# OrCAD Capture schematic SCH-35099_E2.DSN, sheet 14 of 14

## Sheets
14 09 Pmod/UART/I3C: size C
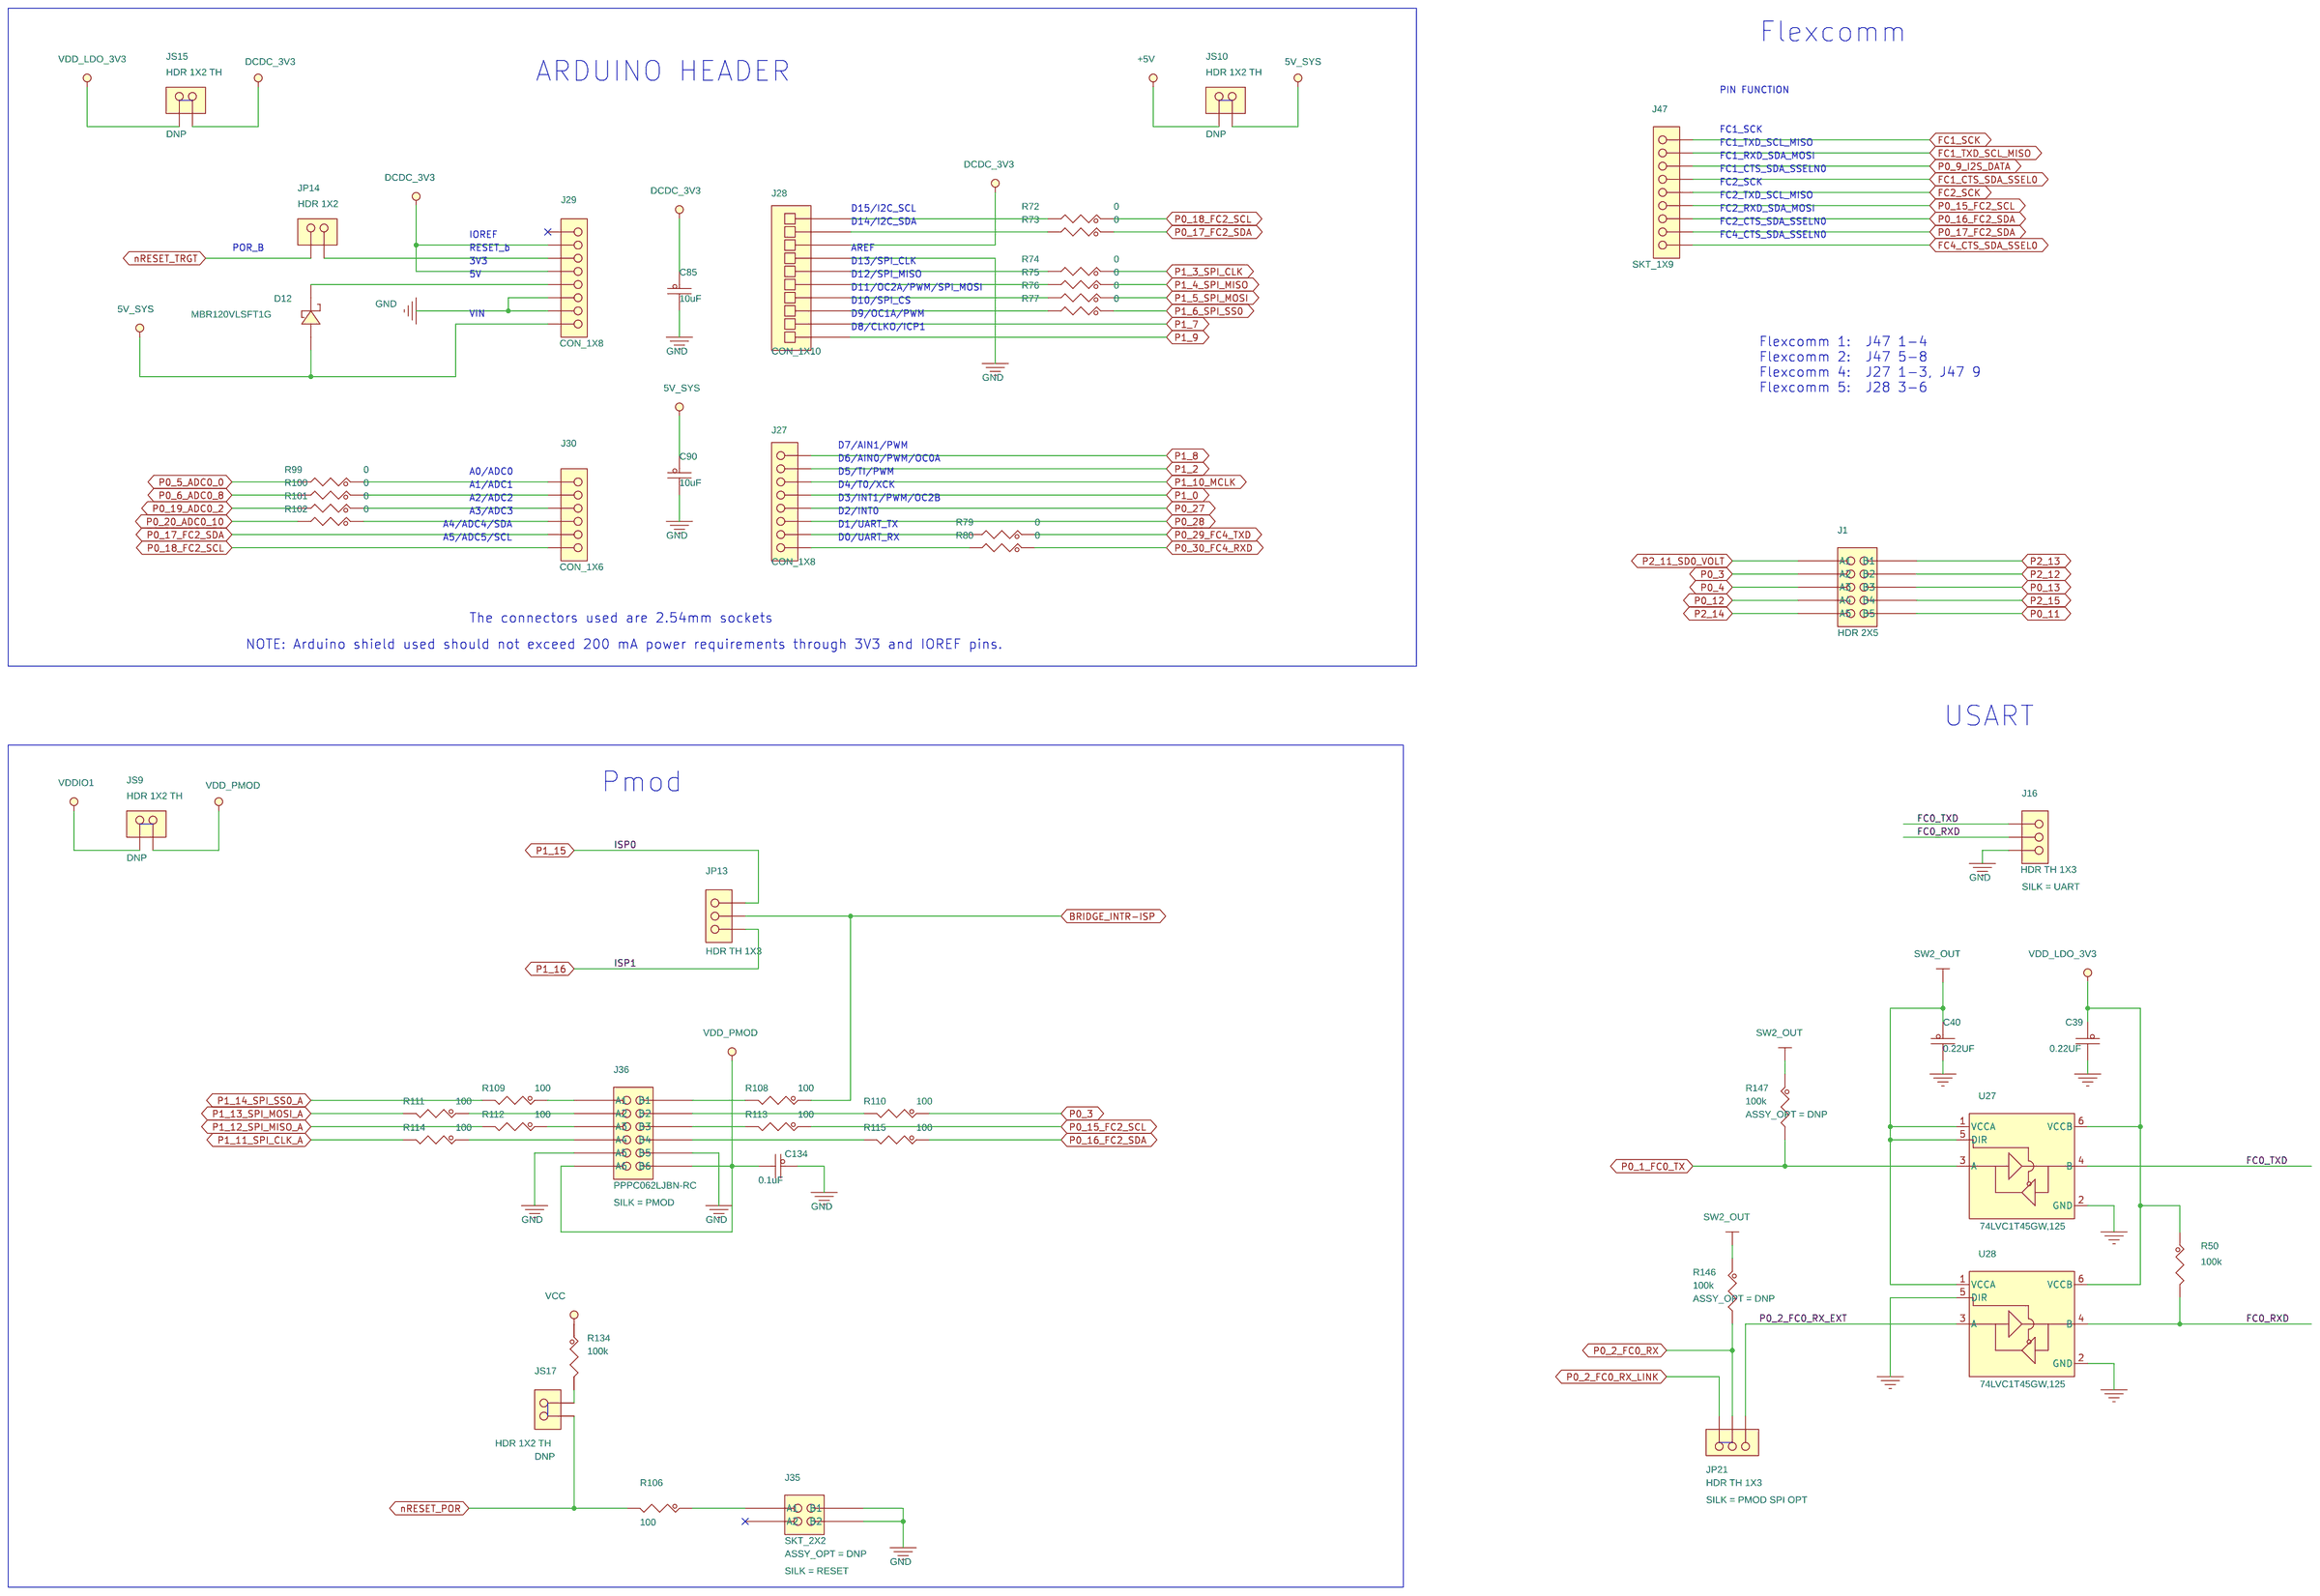
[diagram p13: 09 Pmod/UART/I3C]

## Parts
C39  0.22UF  [CC0402_25]
C40  0.22UF  [CC0402_25]
C85  10uF  [CC0603_OV]
C90  10uF  [CC0603_OV]
C134  0.1uF  [CC0402_25]
D12  MBR120VLSFT1G  [SOD-123]
J1  HDR 2X5  [HDR205]
J16  HDR TH 1X3  [HDR103]
J27  CON_1X8  [con_1x8_skt_2p54_th]
J28  CON_1X10  [HDR110]
J29  CON_1X8  [con_1x8_skt_2p54_th]
J30  CON_1X6  [con_skt1x6_th]
J35  SKT_2X2  [skt2x2_th_ssq]
J36  PPPC062LJBN-RC  [skt2x6_100_th_ra]
J47  SKT_1X9  [con_skt1x9_th]
JP13  HDR TH 1X3  [HDR103]
JP14  HDR 1X2  [HDR102]
JP21  HDR TH 1X3  [HDR103]
JS9  HDR 1X2 TH  [SH_HDR102_BOTTOM]
JS10  HDR 1X2 TH  [SH_HDR102_BOTTOM]
JS15  HDR 1X2 TH  [SH_HDR102_BOTTOM]
JS17  HDR 1X2 TH  [SH_HDR102_BOTTOM]
R50  100k  [RC0402_25]
R72  0  [RC0402_25]
R73  0  [RC0402_25]
R74  0  [RC0402_25]
R75  0  [RC0402_25]
R76  0  [RC0402_25]
R77  0  [RC0402_25]
R79  0  [RC0402_25]
R80  0  [RC0402_25]
R99  0  [RC0402_25]
R100  0  [RC0402_25]
R101  0  [RC0402_25]
R102  0  [RC0402_25]
R106  100  [RC0402_25]
R108  100  [RC0402_25]
R109  100  [RC0402_25]
R110  100  [RC0402_25]
R111  100  [RC0402_25]
R112  100  [RC0402_25]
R113  100  [RC0402_25]
R114  100  [RC0402_25]
R115  100  [RC0402_25]
R134  100k  [RC0402_25]
R146  100k  [RC0402_25]
R147  100k  [RC0402_25]
U27  74LVC1T45GW,125  [SOT-363_0P65_SMT]
U28  74LVC1T45GW,125  [SOT-363_0P65_SMT]

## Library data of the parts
C39 C40 = CAP_NP: CAP CER 0.22UF 16V 10% X5R 0402; AGILE_PN: 150-77913; CAD_APPROVED: Yes; EN: 102-1-01816; FPLIST: CC0402_25,CC0402_HD,0402_CC; HEIGHT: 0.55MM; KEY Number: 102-1-01816@1; MFG_NAME01: TAIYO YUDEN; MFG_PN01: EMK105BJ224KV-F; Mfg: TDK CORPORATION; Mfg Part No: CGA2B1X7R1A224K050*C; Package Size: 0402; ROHS: Yes; Temperature: -55°C to +125°C; Tolerance: 10%; Voltage: 16V
C85 C90 = CAP_NP: CAP CER 10uF 16V 20% X5R 0603; AGILE_PN: 150-80336; CAD_APPROVED: Yes; FPLIST: CC0603_OV,CC0603; HEIGHT: 1MM; MFG_NAME01: MURATA; MFG_PN01: GRM188R61C106MA73D; Package Size: 0603; Package Type: SMD; ROHS: Yes; Tolerance: 20%; VOLTAGE: 16V
C134 = CAP_NP: CAP CER 0.1UF 25V 20% X5R 0402; AGILE_PN: 150-80403; CAD_APPROVED: Yes; FPLIST: CC0402_25,CC0402_HD,0402_CC; HEIGHT: 0.55MM; MFG_NAME01: WURTH ELEKTRONIK EISOS GMBH & CO. KG (ELECTRONIC & ELECTROMEHANICAL COMP); MFG_PN01: 885012105018; ROHS: Yes; Temp Range: -55°C to +85°C; Temp_Range: -55°C to +125°C; VOLTAGE: 25V
D12 = DIODE_SCHTKY: DIODE SCH RECT 1A 20V SMT; AGILE_PN: 480-75997; CAD_APPROVED: Yes; HEIGHT: 1MM; MFG_NAME01: ON SEMICONDUCTOR; ROHS: Yes; VOLTAGE: 20V
J1 = CONN_HDR_5X2: HDR 2X5 TH 100MIL CTR 339H AU 95L; AGILE_PN: 210-30026; CAD_APPROVED: Yes; FPLIST: HDR205,HDR205_CUST; HEIGHT: 8.6MM; MFG_NAME01: SAMTEC; MFG_PN01: TSW-105-07-G-D; ROHS: Yes; Temp Range: -55°C to +125°C
J16 = CONN_HDR_3X1: HDR 1X3 TH 100MIL SP 339H AU 100L; AGILE_PN: 210-75726; CAD_APPROVED: Yes; HEIGHT: 8.65MM; MFG_NAME01: SAMTEC; MFG_PN01: TSW-103-07-G-S; Package Size: 7.62 x 2.54 mm; ROHS: Yes; SILK: UART; Temp Range: -55°C to +125°C; Temp_Range: -55°C to +125°C; VOLTAGE: 450 - 550 VAC
J27 J29 = CONN_HDR_8X1: CON 1X8 SKT TH 100MIL SP 335H AU 104L; AGILE_PN: 210-79539; CAD_APPROVED: Yes; HEIGHT: 8.51MM; MFG_NAME01: SAMTEC; MFG_PN01: SSW-108-01-G-S; ROHS: Yes
J28 = RCPT_1X10: CON 1X10 SKT TH 100MIL SP 335H AU; AGILE_PN: 210-75438; CAD_APPROVED: Yes; HEIGHT: 8.51 MM; MFG_NAME01: SAMTEC; MFG_PN01: SSW-110-01-G-S; Package Size: TH-10; Package Type: TH; ROHS: Yes; VOLTAGE: 550V
J30 = CONN_HDR_6X1: CON 1X6 SKT TH 100MIL SP 335H AU 104L; AGILE_PN: 210-79530; CAD_APPROVED: Yes; HEIGHT: 8.76MM; MFG_NAME01: SAMTEC; MFG_PN01: SSW-106-01-G-S; ROHS: Yes
J35 = CONN_HDR_2X2: CON 2X2 SKT TH 100MIL CTR 340H SN 394L; AGILE_PN: 210-80908; ASSY_OPT: DNP; CAD_APPROVED: Yes; HEIGHT: 8.636MM; MFG_NAME01: Samtec; MFG_PN01: SSQ-102-23-T-D; ROHS: Yes; SILK: RESET
J36 = CONN_HDR_6X2: CON 2X6 SKT RA TH 100MIL CTR 206H AU 124L; AGILE_PN: 210-80998; CAD_APPROVED: Yes; HEIGHT: 5.28 MM; MFG_NAME01: SULLINS ELECTRONICS CORP; ROHS: Yes; SILK: PMOD
J47 = CONN_HDR_9X1: CON 1X9 SKT TH 100MIL SP 340H AU 104L; AGILE_PN: 210-81839; CAD_APPROVED: Yes; HEIGHT: 8.636MM; MFG_NAME01: SAMTEC; MFG_PN01: SSQ-109-01-G-S; ROHS: Yes; Temp Range: -55 to +125C
JP13 = CONN_HDR_3X1: HDR 1X3 TH 100MIL SP 339H AU 100L; AGILE_PN: 210-75726; CAD_APPROVED: Yes; HEIGHT: 8.65MM; MFG_NAME01: SAMTEC; MFG_PN01: TSW-103-07-G-S; Package Size: 7.62 x 2.54 mm; ROHS: Yes; Temp Range: -55°C to +125°C; Temp_Range: -55°C to +125°C; VOLTAGE: 450 - 550 VAC
JP14 = CONN_HDR_2X1: HDR 1X2 TH 100MIL SP 338H SN 100L; AGILE_PN: 210-80102; CAD_APPROVED: Yes; HEIGHT: 8.58MM; MFG_NAME01: SAMTEC; MFG_PN01: TSW-102-07-T-S; Package Size: 5.08 x 2.54 mm; ROHS: Yes
JP21 = CONN_HDR_3X1: HDR 1X3 TH 100MIL SP 339H AU 100L; AGILE_PN: 210-75726; CAD_APPROVED: Yes; HEIGHT: 8.65MM; MFG_NAME01: SAMTEC; MFG_PN01: TSW-103-07-G-S; Package Size: 7.62 x 2.54 mm; ROHS: Yes; SILK: PMOD SPI OPT; Temp Range: -55°C to +125°C; Temp_Range: -55°C to +125°C; VOLTAGE: 450 - 550 VAC
JS9 JS10 JS15 JS17 = CONN_HDR_2X1: HDR 1X2 TH 100MIL SP 339H AU 98L; AGILE_PN: 210-75439; ASSY_OPT: DNP; CAD_APPROVED: YES; FPLIST: HDR102,SH_HDR102_BOTTOM; HEIGHT: 8.71 MM; MFG_NAME01: SAMTEC; MFG_PN01: TSW-102-07-G-S; ROHS: Yes; Temp Range: -55°C to +125°C; Temp_Range: -55°C to +125°C
R50 R134 = RES: RES MF 100K 1/16W 5% 100ppm/C 0402; AGILE_PN: 470-82058; CAD_APPROVED: Yes; FPLIST: RC0402_25,RC0402_HD,0402_CC; HEIGHT: 0.40 MM; MFG_NAME01: YAGEO AMERICA; MFG_PN01: RC0402JR-07100KL; ROHS: Yes; Temp Range: -55C to +155C; Tolerance: 5%; VOLTAGE: 50V
R72-R77 R79 R80 R99-R102 = RES: RES MF ZERO OHM 1/16W 5% 0402; AGILE_PN: 470-75394; CAD_APPROVED: Yes; EN: 101-1-00001; FPLIST: RC0402_25,RC0402_HD,RC0402_X2,0402_CC; HEIGHT: 0.45 MM; KEY Number: 101-1-00001@2; MFG_NAME01: YAGEO AMERICA; MFG_PN01: RC0402JR-070RL; Mfg: VISHAY; Mfg Part No: CRCW04020000Z0**; ROHS: Yes; Temperature: -55°C to +155°C; Tolerance: 5%; VOLTAGE: 1/16W
R106 R108-R115 = RES: RES MF 100 OHM 1/16W 5% 0402; AGILE_PN: 470-82143; CAD_APPROVED: Yes; FPLIST: RC0402_25,RC0402_HD,RC0402_X2,0402_CC; HEIGHT: 0.45MM; MFG_NAME01: YAGEO AMERICA; MFG_PN01: RC0402JR-07100RL; ROHS: Yes; Temp Range: -55°C to +155°C; Tolerance: 5%
R146 R147 = RES: RES MF 100K 1/16W 5% 100ppm/C 0402; AGILE_PN: 470-82058; ASSY_OPT: DNP; CAD_APPROVED: Yes; FPLIST: RC0402_25,RC0402_HD,0402_CC; HEIGHT: 0.40 MM; MFG_NAME01: YAGEO AMERICA; MFG_PN01: RC0402JR-07100KL; ROHS: Yes; Temp Range: -55C to +155C; Tolerance: 5%; VOLTAGE: 50V
U27 U28 = 74LVCH1T45_6P: IC XCVR XLATING DUAL 3-STATE 1.2- 5.5V TSSOP6; AGILE_PN: 312-81277; CAD_APPROVED: Yes; HEIGHT: 1.1MM; MFG_NAME01: NEXPERIA; ROHS: Yes; VOLTAGE: 1.2- 5.5V

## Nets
5V_SYS: C90.1 D12.A J29.8 JS10.1
+5V: JS10.2 ; also on sheet 2 7
GND: C39.2 C40.2 C85.2 C90.2 C134.1 J16.3 J28.7 J29.6 J29.7 J35.2(B1) J35.4(B2) J36.9(A5) J36.10(B5) U27.2(GND) U28.2(GND) U28.5(DIR) ; also on sheet 1 2 3 4 5 7 8 9 10 11 12 13
VDD_LDO_3V3: C39.1 JS15.2 R50.1 U27.6(VCCB) U28.6(VCCB) ; also on sheet 2 7 10
VDD_PMOD: C134.2 J36.11(A6) J36.12(B6) JS9.1
VDDIO1: JS9.2 ; also on sheet 2 4 5 7 8 10 12 13
BRIDGE_INTR-ISP: JP13.2 R108.1 ; also on sheet 11
DCDC_3V3: C85.1 J28.8 J29.2 J29.4 JS15.1
FC0_RXD: J16.2 R50.2 U28.4(B)
FC0_TXD: J16.1 U27.4(B)
FC1_CTS_SDA_SSEL0: J47.4 ; also on sheet 1 8
FC1_SCK: J47.1 ; also on sheet 8
FC1_TXD_SCL_MISO: J47.2 ; also on sheet 8
FC2_SCK: J47.5 ; also on sheet 8
FC4_CTS_SDA_SSEL0: J47.9 ; also on sheet 8
LDO1_OUT: R134.1 ; also on sheet 4 7 8
nRESET_POR: JS17.2 R106.2 ; also on sheet 4
nRESET_TRGT: JP14.2 ; also on sheet 4 5 7 10 12
P0_1_FC0_TX: R147.2 U27.3(A) ; also on sheet 8 11
P0_2_FC0_RX: JP21.2 R146.2 ; also on sheet 8
P0_2_FC0_RX_EXT: JP21.3 U28.3(A)
P0_2_FC0_RX_LINK: JP21.1 ; also on sheet 11
P0_3: J1.3(A2) R110.1 ; also on sheet 3 8
P0_4: J1.5(A3) ; also on sheet 3 8
P0_5_ADC0_0: R99.2 ; also on sheet 8
P0_6_ADC0_8: R100.2 ; also on sheet 8
P0_9_I2S_DATA: J47.3 ; also on sheet 8 13
P0_11: J1.10(B5) ; also on sheet 1 8
P0_12: J1.7(A4) ; also on sheet 3 8
P0_13: J1.6(B3) ; also on sheet 3 8
P0_15_FC2_SCL: J47.6 R113.1 ; also on sheet 8 12
P0_16_FC2_SDA: J47.7 R115.1 ; also on sheet 8 12
P0_17_FC2_SDA: J30.5 J47.8 R73.1 ; also on sheet 8 10
P0_18_FC2_SCL: J30.6 R72.1 ; also on sheet 8 10
P0_19_ADC0_2: R101.2 ; also on sheet 8
P0_20_ADC0_10: R102.2 ; also on sheet 8
P0_27: J27.4 ; also on sheet 8
P0_28: J27.3 ; also on sheet 8
P0_29_FC4_TXD: R79.1 ; also on sheet 8
P0_30_FC4_RXD: R80.1 ; also on sheet 8
P1_0: J27.5 ; also on sheet 8
P1_2: J27.7 ; also on sheet 8
P1_3_SPI_CLK: R74.1 ; also on sheet 8
P1_4_SPI_MISO: R75.1 ; also on sheet 3 8
P1_5_SPI_MOSI: R76.1 ; also on sheet 3 8 10
P1_6_SPI_SS0: R77.1 ; also on sheet 3 8
P1_7: J28.2 ; also on sheet 3 4 8
P1_8: J27.8 ; also on sheet 3 8
P1_9: J28.1 ; also on sheet 8
P1_10_MCLK: J27.6 ; also on sheet 8 13
P1_11_SPI_CLK_A: R114.2 ; also on sheet 9 11
P1_12_SPI_MISO_A: R112.2 ; also on sheet 9 11
P1_13_SPI_MOSI_A: R111.2 ; also on sheet 9 11
P1_14_SPI_SS0_A: R109.2 ; also on sheet 9 11
P1_15: JP13.3 ; also on sheet 8
P1_16: JP13.1 ; also on sheet 8
P2_11_SD0_VOLT: J1.1(A1) ; also on sheet 3 8
P2_12: J1.4(B2) ; also on sheet 4 8
P2_13: J1.2(B1) ; also on sheet 8
P2_14: J1.9(A5) ; also on sheet 8
P2_15: J1.8(B4) ; also on sheet 8
SW2_OUT: C40.1 R146.1 R147.1 U27.1(VCCA) U27.5(DIR) U28.1(VCCA) ; also on sheet 1 3 4 5 7 8 9 10 11 13
N16974908: J36.1(A1) R109.1
N16974910: J36.2(B1) R108.2
N16974934: J36.3(A2) R111.1
N16974944: J36.4(B2) R110.2
N16974979: J36.5(A3) R112.1
N16974981: J36.6(B3) R113.2
N16975000: J36.7(A4) R114.1
N16975002: J36.8(B4) R115.2
N16975069: J35.1(A1) R106.1
N17759955: J28.10 R72.2
N17759973: J28.9 R73.2
N17759990: J29.3 JP14.1
N17760012: J28.6 R74.2
N17760030: D12.C J29.5
N17760042: J28.5 R75.2
N17760075: J28.4 R76.2
N17760099: J28.3 R77.2
N17760234: J30.1 R99.1
N17760260: J30.2 R100.1
N17760297: J30.3 R101.1
N17760315: J30.4 R102.1
N17760343: J27.2 R79.2
N17760363: J27.1 R80.2
N18503998: JS17.1 R134.2

Not connected (* = marked no-connect by the designer): J29 1*; J35 3(A2)*

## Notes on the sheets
sheet 14
- Flexcomm
- ARDUINO HEADER
- PIN FUNCTION
- FC1_SCK
- FC1_RXD_SDA_MOSI
- FC1_TXD_SCL_MISO
- FC1_CTS_SDA_SSELN0
- FC2_SCK
- FC2_TXD_SCL_MISO
- D15/I2C_SCL
- FC2_RXD_SDA_MOSI
- D14/I2C_SDA
- FC2_CTS_SDA_SSELN0
- POR_B
- IOREF
- RESET_b
- AREF
- FC4_CTS_SDA_SSELN0
- 3V3
- D13/SPI_CLK
- 5V
- D12/SPI_MISO
- D11/OC2A/PWM/SPI_MOSI
- D10/SPI_CS
- VIN
- D8/CLKO/ICP1
- D9/OC1A/PWM
- Flexcomm 1:  J47 1-4
  Flexcomm 2:  J47 5-8
  Flexcomm 4:  J27 1-3, J47 9
  Flexcomm 5:  J28 3-6
- D7/AIN1/PWM
- D6/AIN0/PWM/OC0A
- A0/ADC0
- D5/TI/PWM
- A1/ADC1
- A2/ADC2
- D3/INT1/PWM/OC2B
- D4/T0/XCK
- A3/ADC3
- D2/INT0
- A4/ADC4/SDA
- D1/UART_TX
- A5/ADC5/SCL
- D0/UART_RX
- The connectors used are 2.54mm sockets
- NOTE: Arduino shield used should not exceed 200 mA power requirements through 3V3 and IOREF pins.
- USART
- Pmod
